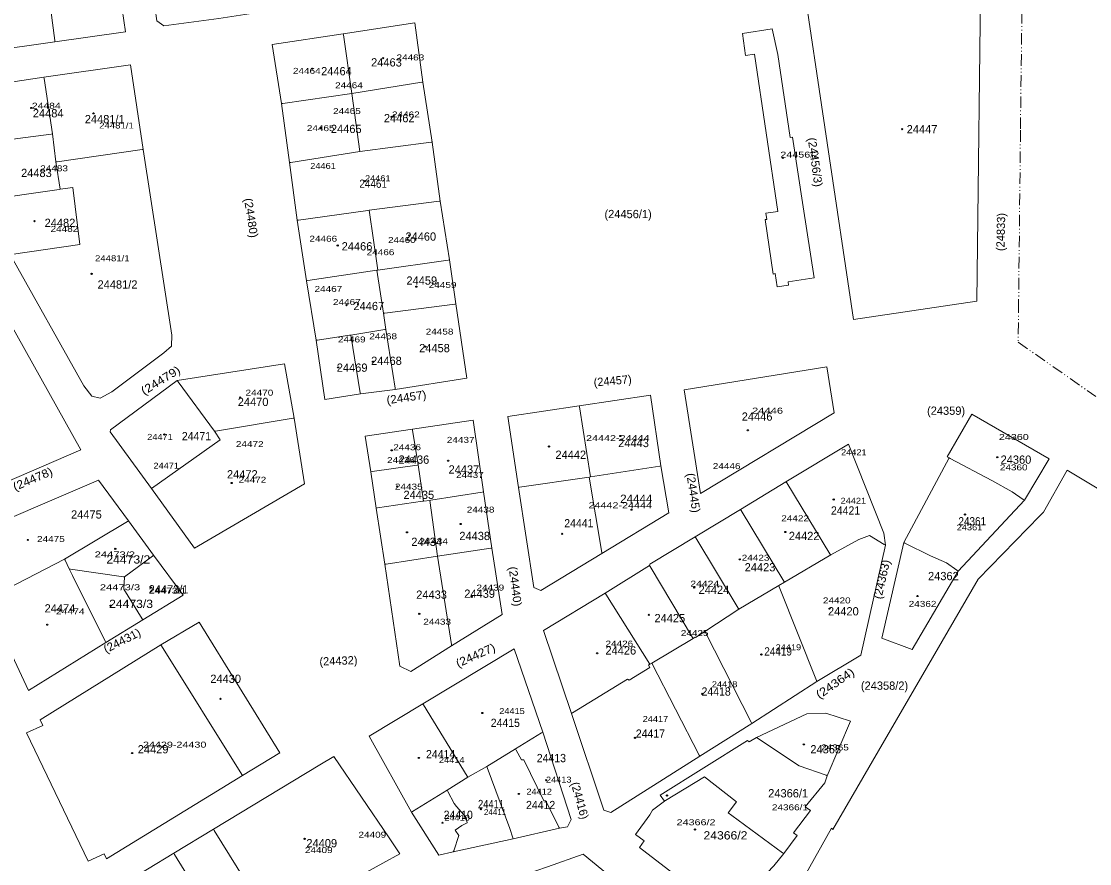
# Model space of a CAD drawing. Extents: x 649608 to 651081, y 237980 to 241202.
# Drawn here: x 650118.4 to 650584.2, y 239073.7 to 239440.9 of the extents above; entities that cross this region are included whole.
import ezdxf

# ---------------------------------------------------------------- set-up
doc = ezdxf.new("R2010")
doc.units = 0
doc.header["$PDMODE"] = 32
doc.header["$PDSIZE"] = 0.5
doc.linetypes.add('DASH_DOUBLE_DOT', pattern=[9.2, 5, -1.2, 0.3, -1.2, 0.3, -1.2])
for name, color, linetype in [('19', 7, 'Continuous'), ('20', 7, 'Continuous'), ('6', 7, 'Continuous')]:
    doc.layers.add(name, color=color, linetype=linetype)
for name, color, linetype, lineweight in [('3', 7, 'Continuous', 13), ('5', 7, 'Continuous', 13), ('52', 7, 'DASH_DOUBLE_DOT', 13)]:
    doc.layers.add(name, color=color, linetype=linetype, lineweight=lineweight)

msp = doc.modelspace()

# ---------------------------------------------------------------- linework, layer by layer
at = {"layer": '3'}
for p, q in [((650330.495, 239268.665), (650335.104, 239237.703)), ((650195.93, 239178.982), (650179.209, 239169.1)), ((650270.101, 239129.252), (650293.391, 239143.387))]:
    msp.add_line(p, q, dxfattribs=at)
for points in [[(650132.999, 239431.986), (650163.748, 239436.339), (650158.694, 239471.073), (650153.145, 239505.429)], [(650046.003, 239490.267), (650068.149, 239425.852), (650072.472, 239423.448), (650132.999, 239431.986)], [(650173.133, 239472.727), (650177.495, 239441.151), (650180.595, 239439.009), (650204.517, 239442.103), (650229.032, 239445.95)], [(650293.467, 239414.388), (650289.92, 239440.208), (650258.76, 239435.456), (650227.771, 239430.73)], [(650227.771, 239430.73), (650231.896, 239405.03), (650235.382, 239379.31), (650238.693, 239354.152), (650242.788, 239327.791), (650247.014, 239301.863), (650250.767, 239275.951)], [(650128.237, 239416.516), (650166.016, 239421.899), (650171.539, 239385.019)], [(650076.272, 239405.643), (650078.266, 239409.41), (650113.744, 239414.433), (650128.237, 239416.516)], [(650281.432, 239280.399), (650312.635, 239285.281), (650307.885, 239317.712), (650305.012, 239336.858), (650301.059, 239362.538), (650297.586, 239388.282), (650293.467, 239414.388)], [(650171.539, 239385.019), (650183.987, 239304.061), (650183.875, 239299.271), (650180.56, 239296.372), (650157.812, 239279.426), (650152.812, 239276.665), (650149.116, 239277.45), (650145.625, 239281.94), (650113.519, 239339.195), (650100.824, 239362.641), (650087.843, 239385.509), (650076.272, 239405.643)], [(650060.24, 239277.75), (650083.957, 239228.008), (650144.359, 239254.095), (650116.406, 239304.12), (650104.179, 239325.641)], [(650186.368, 239284.25), (650233.175, 239291.556), (650237.391, 239267.923)], [(650175.143, 239237.286), (650157.095, 239261.932), (650157.203, 239262.764), (650186.368, 239284.25)], [(650250.767, 239275.951), (650266.206, 239278.446), (650281.432, 239280.399)], [(650397.276, 239247.076), (650392.689, 239277.913), (650361.643, 239273.3), (650330.495, 239268.665)], [(650237.391, 239267.923), (650241.902, 239239.195), (650193.948, 239211.272), (650175.143, 239237.286)], [(650288.931, 239263.156), (650315.327, 239266.984), (650319.853, 239235.726), (650323.533, 239211.269)], [(650522.897, 239250.587), (650522.128, 239251.077), (650532.835, 239269.607)], [(650532.835, 239269.607), (650566.587, 239250.109), (650555.741, 239232.08), (650526.822, 239201.233)], [(650270.796, 239244.503), (650268.365, 239259.987), (650288.931, 239263.156)], [(650495.119, 239212.56), (650494.485, 239217.742), (650479.06, 239256.559), (650451.789, 239240.133), (650431.896, 239228.079), (650412.207, 239216.17)], [(650526.822, 239201.233), (650506.836, 239166.998), (650493.611, 239171.954), (650503.175, 239213.663), (650522.897, 239250.587)], [(650288.284, 239157.444), (650283.38, 239159.794), (650276.896, 239204.165), (650273.117, 239228.674), (650270.796, 239244.503)], [(650371.557, 239208.851), (650400.646, 239226.576), (650397.276, 239247.076)], [(650634.917, 238992.051), (650633.914, 238992.9), (650730.416, 239151.667), (650574.402, 239245.255), (650564.003, 239226.917), (650562.503, 239225.238), (650535.575, 239197.674), (650472.242, 239088.563), (650471.65, 239089.049), (650460.092, 239068.577)], [(650090.509, 239214.51), (650152.062, 239240.917), (650165.182, 239223.066), (650176.051, 239208.081)], [(650335.104, 239237.703), (650341.856, 239194.021), (650344.896, 239192.683), (650371.557, 239208.851)], [(650412.207, 239216.17), (650392.391, 239204.249), (650392.228, 239203.646), (650372.914, 239191.628)], [(650155.215, 239170.116), (650121.458, 239149.195), (650102.881, 239188.672), (650090.509, 239214.51)], [(650323.533, 239211.269), (650328.063, 239182.321), (650306.018, 239168.654), (650288.284, 239157.444)], [(650465.274, 239153.018), (650484.449, 239164.517), (650495.119, 239212.56)], [(650176.051, 239208.081), (650189.021, 239190.76), (650171.323, 239179.927), (650155.215, 239170.116)], [(650372.914, 239191.628), (650346.122, 239175.24), (650358.212, 239139.109)], [(650179.209, 239169.1), (650126.623, 239136.422), (650127.702, 239133.842), (650120.58, 239130.619), (650147.461, 239074.664), (650154.456, 239077.914), (650155.512, 239075.737), (650214.814, 239112.02), (650231.127, 239121.93), (650195.93, 239178.982)], [(650293.391, 239143.387), (650333.248, 239167.27), (650345.736, 239130.955)], [(650375.348, 239095.929), (650414.213, 239120.505), (650436.928, 239134.803), (650465.274, 239153.018)], [(650358.212, 239139.109), (650372.327, 239097.018), (650375.348, 239095.929)], [(650438.899, 239128.695), (650460.839, 239138.937), (650469.181, 239139.313), (650479.971, 239135.731), (650469.797, 239111.997)], [(650306.724, 239078.733), (650300.372, 239077.317), (650288.478, 239096.054), (650270.101, 239129.252)], [(650345.736, 239130.955), (650358.159, 239092.929), (650356.498, 239089.714), (650353.01, 239089.125), (650332.812, 239084.431), (650306.724, 239078.733)], [(650398.749, 239100.87), (650396.896, 239103.447), (650435.016, 239127.346), (650435.782, 239126.731), (650438.899, 239128.695)], [(650254.614, 239120.424), (650248.579, 239116.678), (650202.232, 239088.667), (650184.817, 239078.16)], [(650254.614, 239120.424), (650278.724, 239084.856), (650283.368, 239077.865), (650276.074, 239073.838)], [(650469.797, 239111.997), (650468.668, 239108.943), (650460.114, 239098.437), (650462.495, 239096.89), (650455.041, 239087.153), (650456.724, 239085.946), (650450.824, 239078.036)], [(650450.824, 239078.036), (650446.42, 239072.723), (650443.555, 239069.71), (650439.954, 239067.534), (650435.893, 239066.089), (650431.679, 239065.666), (650406.177, 239066.662), (650387.929, 239080.729), (650389.909, 239083.539), (650386.225, 239086.383), (650392.442, 239094.932), (650393.624, 239097.016), (650398.749, 239100.87)], [(650184.817, 239078.16), (650161.861, 239064.266), (650173.208, 239041.436)], [(650381.221, 239063.049), (650363.393, 239077.851), (650347.856, 239072.254), (650337.653, 239068.717)], [(650173.208, 239041.436), (650182.485, 239021.849), (650212.074, 239038.491), (650229.817, 239048.491), (650276.074, 239073.838)]]:
    msp.add_lwpolyline(points, dxfattribs=at)
for points in [[(650458.309, 239465.099), (650536.901, 239476.918), (650535.05, 239318.891), (650481.294, 239310.911)], [(650438.095, 239426.546), (650434.205, 239425.967), (650432.822, 239435.663), (650445.756, 239437.595), (650448.188, 239426.458), (650453.632, 239390.31), (650454.64, 239390.385), (650459.338, 239359.968), (650464.101, 239329.126), (650452.757, 239327.38), (650452.847, 239325.838), (650447.946, 239325.133), (650447.026, 239330.943), (650446.215, 239330.738), (650442.672, 239354.571), (650443.426, 239354.528), (650443.036, 239357.195), (650448.292, 239358.041)], [(650407.42, 239280.25), (650414.538, 239234.995), (650472.786, 239270.246), (650469.656, 239290.218)]]:
    msp.add_lwpolyline(points, close=True, dxfattribs=at)
at = {"layer": '5'}
for p, q in [((650273.859, 239332.471), (650270.036, 239358.518)), ((650273.415, 239332.408), (650273.859, 239332.471)), ((650102.881, 239188.672), (650137.202, 239206.437))]:
    msp.add_line(p, q, dxfattribs=at)
for points in [[(650132.999, 239431.986), (650132.935, 239432.486), (650128.533, 239466.816)], [(650258.76, 239435.456), (650258.819, 239435.048), (650262.488, 239409.451), (650266.022, 239384.128)], [(650128.237, 239416.516), (650128.311, 239416.016), (650131.91, 239391.803), (650133.48, 239379.637), (650135.357, 239367.722)], [(650262.488, 239409.451), (650292.967, 239414.308), (650293.467, 239414.388)], [(650262.488, 239409.451), (650232.396, 239405.102), (650231.896, 239405.03)], [(650131.91, 239391.803), (650131.41, 239391.734), (650116.932, 239389.749), (650087.843, 239385.509)], [(650266.022, 239384.128), (650297.086, 239388.216), (650297.586, 239388.282)], [(650171.539, 239385.019), (650171.039, 239384.948), (650133.98, 239379.708), (650133.48, 239379.637)], [(650266.022, 239384.128), (650235.882, 239379.389), (650235.382, 239379.31)], [(650135.357, 239367.722), (650134.857, 239367.648), (650101.324, 239362.715), (650100.824, 239362.641)], [(650135.357, 239367.722), (650140.827, 239368.411), (650143.963, 239343.627), (650114.019, 239339.268), (650113.519, 239339.195)], [(650270.036, 239358.518), (650300.559, 239362.473), (650301.059, 239362.538)], [(650270.036, 239358.518), (650269.536, 239358.448), (650239.193, 239354.222), (650238.693, 239354.152)], [(650273.859, 239332.471), (650304.512, 239336.788), (650305.012, 239336.858)], [(650273.415, 239332.408), (650243.288, 239327.866), (650242.788, 239327.791)], [(650281.432, 239280.399), (650281.353, 239280.899), (650277.315, 239306.605), (650276.347, 239313.633), (650273.415, 239332.408)], [(650276.347, 239313.633), (650276.847, 239313.698), (650307.385, 239317.647), (650307.885, 239317.712)], [(650262.001, 239304.107), (650276.815, 239306.523), (650277.315, 239306.605)], [(650262.001, 239304.107), (650261.501, 239304.032), (650247.514, 239301.938), (650247.014, 239301.863)], [(650266.206, 239278.446), (650266.124, 239278.946), (650262.001, 239304.107)], [(650202.572, 239262.164), (650186.735, 239283.75), (650186.368, 239284.25)], [(650361.643, 239273.3), (650361.723, 239272.8), (650366.622, 239242.311)], [(650202.572, 239262.164), (650203.072, 239262.247), (650236.891, 239267.84), (650237.391, 239267.923)], [(650288.931, 239263.156), (650289.01, 239262.656), (650291.407, 239247.473), (650293.78, 239231.717), (650296.457, 239232.051), (650299.787, 239207.752)], [(650175.143, 239237.286), (650205.149, 239258.463), (650202.572, 239262.164)], [(650522.897, 239250.587), (650523.397, 239250.321), (650541.494, 239240.686), (650550.391, 239235.807), (650555.241, 239232.428), (650555.741, 239232.08)], [(650270.796, 239244.503), (650271.296, 239244.575), (650290.907, 239247.401), (650291.407, 239247.473)], [(650366.622, 239242.311), (650396.776, 239246.998), (650397.276, 239247.076)], [(650335.104, 239237.703), (650335.604, 239237.776), (650366.023, 239242.218), (650366.622, 239242.311)], [(650366.023, 239242.218), (650371.474, 239209.351), (650371.557, 239208.851)], [(650471.278, 239208.225), (650470.973, 239208.725), (650452.094, 239239.633), (650451.789, 239240.133)], [(650296.457, 239232.051), (650296.957, 239232.13), (650319.353, 239235.647), (650319.853, 239235.726)], [(650273.117, 239228.674), (650273.617, 239228.748), (650293.28, 239231.643), (650293.78, 239231.717)], [(650451.189, 239196.375), (650450.885, 239196.875), (650432.2, 239227.579), (650431.896, 239228.079)], [(650137.202, 239206.437), (650164.682, 239222.769), (650165.182, 239223.066)], [(650431.197, 239184.578), (650430.896, 239185.078), (650412.508, 239215.67), (650412.207, 239216.17)], [(650471.278, 239208.225), (650483.522, 239215.043), (650488.242, 239216.671), (650494.619, 239212.859), (650495.119, 239212.56)], [(650299.787, 239207.752), (650323.033, 239211.195), (650323.533, 239211.269)], [(650503.175, 239213.663), (650503.675, 239213.415), (650514.845, 239207.874), (650521.796, 239204.804), (650526.322, 239201.588), (650526.822, 239201.233)], [(650137.202, 239206.437), (650137.444, 239205.937), (650139.264, 239202.185)], [(650163.444, 239198.697), (650175.551, 239207.709), (650176.051, 239208.081)], [(650276.896, 239204.165), (650277.396, 239204.243), (650299.787, 239207.752)], [(650299.787, 239207.752), (650305.938, 239169.154), (650306.018, 239168.654)], [(650411.341, 239171.797), (650412.197, 239172.449), (650412.318, 239172.192), (650416.372, 239174.908), (650431.197, 239184.578), (650448.636, 239194.87), (650451.189, 239196.375), (650471.278, 239208.225)], [(650139.264, 239202.185), (650140.698, 239199.35), (650154.967, 239170.616), (650155.215, 239170.116)], [(650139.264, 239202.185), (650139.764, 239202.113), (650162.944, 239198.769), (650163.444, 239198.697)], [(650411.341, 239171.797), (650411.041, 239172.297), (650392.528, 239203.146), (650392.228, 239203.646)], [(650171.323, 239179.927), (650171.012, 239180.427), (650163.021, 239193.254), (650163.444, 239198.697)], [(650448.636, 239194.87), (650448.835, 239194.37), (650465.075, 239153.518), (650465.274, 239153.018)], [(650392.443, 239160.617), (650373.229, 239191.128), (650372.914, 239191.628)], [(650416.372, 239174.908), (650416.628, 239174.408), (650436.672, 239135.303), (650436.928, 239134.803)], [(650358.212, 239139.109), (650358.712, 239139.415), (650382.744, 239154.124), (650383.392, 239153.627), (650392.438, 239159.14), (650391.903, 239160.196), (650392.443, 239160.617), (650393.287, 239161.058), (650411.341, 239171.797)], [(650179.209, 239169.1), (650179.521, 239168.6), (650214.502, 239112.52), (650214.814, 239112.02)], [(650393.287, 239161.058), (650413.955, 239121.005), (650414.213, 239120.505)], [(650293.391, 239143.387), (650293.699, 239142.887), (650312.821, 239111.85), (650313.129, 239111.35)], [(650333.91, 239123.656), (650345.236, 239130.646), (650345.736, 239130.955)], [(650438.899, 239128.695), (650457.463, 239116.286), (650469.297, 239112.171), (650469.797, 239111.997)], [(650288.478, 239096.054), (650288.978, 239096.361), (650304.084, 239105.65), (650313.129, 239111.35), (650321.295, 239116.052), (650333.91, 239123.656)], [(650333.91, 239123.656), (650334.18, 239123.156), (650336.472, 239118.913), (650337.433, 239118.918), (650346.234, 239101.106), (650347.017, 239101.013), (650352.758, 239089.625), (650353.01, 239089.125)], [(650321.295, 239116.052), (650321.482, 239115.552), (650331.384, 239089.011), (650332.656, 239084.931), (650332.812, 239084.431)], [(650398.749, 239100.87), (650399.249, 239101.171), (650416.291, 239111.439), (650430.235, 239100.653), (650426.596, 239095.745), (650428.105, 239094.642), (650450.324, 239078.401), (650450.824, 239078.036)], [(650304.084, 239105.65), (650304.344, 239105.15), (650307.095, 239099.865), (650308.17, 239098.499), (650312.363, 239093.73), (650312.737, 239091.436), (650310.444, 239090.272), (650307.525, 239088.18), (650309.185, 239085.979), (650306.894, 239079.233), (650306.724, 239078.733)], [(650215.882, 239066.55), (650202.541, 239088.167), (650202.232, 239088.667)], [(650184.817, 239078.16), (650185.127, 239077.66), (650197.855, 239057.151), (650198.165, 239056.651)]]:
    msp.add_lwpolyline(points, dxfattribs=at)
at = {"layer": '52'}
msp.add_lwpolyline([(650605.404, 240765.589), (650575.102, 240622.376), (650564.111, 240019.547), (650563.292, 239912.239), (650561.967, 239831.306), (650558.948, 239635.138), (650557.76, 239590.469), (650555.824, 239499.761), (650555.114, 239481.758), (650553.994, 239393.396), (650554.019, 239393.395), (650553.222, 239318.763), (650553.006, 239301.006), (650586.911, 239277.281)], dxfattribs=at)
at = {"layer": '6'}
for p in [(650276.158, 239424.829), (650245.198, 239420.243), (650122.715, 239403.132), (650149.879, 239400.768), (650279.882, 239399.258), (650248.965, 239394.38), (650502.425, 239393.914), (650450.427, 239381.364), (650268.168, 239371.217), (650124.142, 239353.803), (650287.513, 239347.504), (650256.346, 239343.154), (650149.036, 239330.842), (650290.644, 239325.245), (650260.162, 239317.135), (650294.559, 239299.055), (650256.518, 239290.029), (650271.713, 239292.525), (650213.793, 239276.86), (650435.178, 239262.606), (650180.746, 239260.768), (650379.549, 239260.112), (650279.868, 239253.829), (650348.479, 239255.501), (650304.495, 239249.35), (650543.906, 239250.843), (650210.128, 239239.597), (650282.281, 239238.073), (650472.59, 239232.392), (650384.403, 239227.963), (650529.837, 239225.91), (650309.914, 239221.739), (650286.557, 239218.108), (650354.183, 239217.45), (650451.514, 239218.254), (650121.217, 239214.794), (650159.35, 239210.881), (650431.628, 239206.328), (650174.836, 239194.004), (650411.785, 239193.983), (650314.745, 239189.961), (650509.141, 239190.33), (650157.35, 239186.15), (650470.793, 239184.844), (650291.922, 239182.598), (650392.017, 239182.131), (650129.691, 239177.816), (650369.438, 239165.368), (650441.055, 239164.836), (650415.246, 239147.706), (650205.257, 239145.501), (650319.383, 239139.31), (650385.932, 239128.493), (650459.549, 239125.655), (650166.72, 239121.882), (650291.675, 239119.72), (650347.194, 239110.04), (650335.279, 239104.043), (650399.923, 239103.365), (650318.7, 239097.392), (650302.054, 239091.483), (650412.119, 239088.552), (650241.91, 239084.457)]:
    msp.add_point(p, dxfattribs=at)

# ---------------------------------------------------------------- texts
at = {"layer": '19'}
for s, p in [('24464', (650249.092, 239417.37)), ('24463', (650270.894, 239421.209)), ('24484', (650123.404, 239399.027)), ('24481/1', (650146.061, 239396.466)), ('24462', (650276.452, 239396.893)), ('24465', (650253.367, 239392.2)), ('24447', (650504.418, 239392.073)), ('24483', (650118.274, 239373.004)), ('(24456/1)', (650372.643, 239355.085)), ('24482', (650128.534, 239351.246)), ('24460', (650285.858, 239345.272)), ('24466', (650258.07, 239341.007)), ('24481/2', (650151.619, 239324.369)), ('24459', (650286.285, 239326.075)), ('24467', (650263.201, 239314.984)), ('24458', (650291.843, 239296.639)), ('24469', (650255.933, 239288.107)), ('24468', (650270.895, 239291.094)), ('24470', (650212.754, 239273.176)), ('(24359)', (650513.295, 239269.336)), ('24446', (650432.495, 239266.776)), ('24443', (650378.628, 239255.258)), ('24442', (650351.267, 239250.139)), ('24436', (650282.866, 239248.005)), ('24360', (650545.357, 239248.006)), ('24472', (650208.052, 239241.607)), ('24437', (650304.669, 239243.739)), ('24435', (650285.004, 239232.647)), ('24475', (650140.076, 239224.116)), ('24434', (650288.424, 239212.17)), ('24438', (650309.372, 239214.73)), ('24422', (650453.016, 239214.731)), ('24423', (650433.778, 239201.079)), ('24362', (650513.723, 239197.24)), ('24473/1', (650173.895, 239191.462)), ('24433', (650290.561, 239189.133)), ('24439', (650311.509, 239189.56)), ('24424', (650413.685, 239191.267)), ('24474', (650128.534, 239183.161)), ('24420', (650470.116, 239181.882)), ('24425', (650394.447, 239178.895)), ('24426', (650373.071, 239164.817)), ('24430', (650200.784, 239152.446)), ('(24358/2)', (650484.448, 239149.462)), ('24429', (650169.147, 239121.73)), ('24365', (650462.421, 239121.729)), ('24366/1', (650444.038, 239102.532)), ('24409', (650242.679, 239080.775))]:
    msp.add_text(s, height=3.6, dxfattribs=at).set_placement(p)
for s, rotation, width, p in [('(24456/3)', 277.87, 1.05, (650461.252, 239389.971)), ('(24480)', 278.864, 1.05, (650215.461, 239363.535)), ('(24479)', 31.951, 1.15, (650171.95, 239277.796)), ('(24457)', 8.252, 1.05, (650277.91, 239273.939)), ('(24478)', 23.35, 1.1, (650115.688, 239236.11)), ('(24445)', 278.55, 1.05, (650408.357, 239243.676)), ('(24440)', 277.447, 1.05, (650330.856, 239202.939)), ('(24363)', 77.085, 1.05, (650493.356, 239188.738)), ('(24431)', 27.059, 1.05, (650155.354, 239165.313)), ('(24427)', 24.578, 1.1, (650308.867, 239159.072)), ('(24364)', 35.193, 1.15, (650466.417, 239145.331))]:
    msp.add_text(s, height=3.6, rotation=rotation, dxfattribs=dict(at, width=width)).set_placement(p)
for s, width, p in [('24461', 0.9, (650265.764, 239368.31)), ('24471', 0.95, (650188.386, 239258.245)), ('24444', 1.05, (650379.482, 239230.942)), ('24421', 0.95, (650471.399, 239225.823)), ('24441', 0.95, (650355.115, 239220.276)), ('24361', 0.9, (650526.975, 239221.13)), ('24473/2', 1.1, (650155.467, 239204.492)), ('24473/3', 1.1, (650156.663, 239185.124)), ('24419', 0.9, (650442.327, 239164.391)), ('24418', 0.95, (650414.967, 239146.9)), ('24415', 0.95, (650323.053, 239133.247)), ('24417', 0.95, (650386.323, 239128.555)), ('24414', 0.95, (650294.838, 239119.595)), ('24413', 0.95, (650343.146, 239117.89)), ('24411', 0.85, (650317.495, 239097.839)), ('24412', 0.95, (650338.443, 239097.412)), ('24410', 0.95, (650302.532, 239093.146)), ('24366/2', 1.1, (650415.821, 239084.187))]:
    msp.add_text(s, height=3.6, dxfattribs=dict(at, width=width)).set_placement(p)
for s, rotation, p in [('(24833)', 88.718, (650547.041, 239340.718)), ('(24457)', 4.998, (650368.09, 239281.691)), ('(24432)', 2.298, (650248.433, 239159.975)), ('(24416)', 285.699, (650357.944, 239108.665))]:
    msp.add_text(s, height=3.6, rotation=rotation, dxfattribs=at).set_placement(p)
at = {"layer": '20'}
for s, width, p in [('24463', 1.25, (650281.982, 239423.857)), ('24464', 1.25, (650236.806, 239418.007)), ('24464', 1.25, (650255.19, 239411.724)), ('24484', 1.3, (650122.979, 239402.807)), ('24465', 1.25, (650254.297, 239400.472)), ('24462', 1.25, (650279.99, 239398.993)), ('24481/1', 1.2, (650152.337, 239394.177)), ('24465', 1.25, (650242.873, 239393.029)), ('24456/2', 1.35, (650449.31, 239381.488)), ('24461', 1.15, (650244.371, 239376.561)), ('24483', 1.25, (650126.636, 239375.505)), ('24461', 1.15, (650268.239, 239371.186)), ('24482', 1.25, (650131.133, 239349.103)), ('24466', 1.25, (650244.006, 239344.825)), ('24460', 1.25, (650278.263, 239344.28)), ('24466', 1.25, (650268.962, 239338.948)), ('24481/1', 1.2, (650150.525, 239336.322)), ('24467', 1.25, (650246.235, 239322.942)), ('24459', 1.25, (650296.034, 239324.696)), ('24467', 1.25, (650254.266, 239317.197)), ('24468', 1.25, (650270.118, 239302.283)), ('24458', 1.25, (650294.714, 239304.328)), ('24469', 1.25, (650256.411, 239300.9)), ('24470', 1.25, (650216.159, 239277.693)), ('24446 ', 1.4, (650436.981, 239269.866)), ('24471', 1.15, (650173.283, 239258.419)), ('24472', 1.25, (650211.94, 239255.282)), ('24437', 1.25, (650303.911, 239257.12)), ('24442-24444', 1.35, (650364.622, 239257.871)), ('24360 ', 1.35, (650544.597, 239258.381)), ('24436', 1.25, (650280.566, 239253.914)), ('24421', 1.15, (650475.808, 239251.719)), ('24471', 1.15, (650176.001, 239245.851)), ('24436', 1.25, (650277.853, 239248.284)), ('24437', 1.25, (650307.922, 239241.832)), ('24446', 1.25, (650419.866, 239245.677)), ('24360', 1.25, (650545.032, 239245.113)), ('24472', 1.25, (650213.08, 239239.709)), ('24435', 1.25, (650281.28, 239236.728)), ('24442-24444', 1.35, (650365.694, 239228.614)), ('24421', 1.15, (650475.62, 239230.579)), ('24438', 1.25, (650312.597, 239226.712)), ('24422', 1.25, (650449.732, 239222.951)), ('24361', 1.15, (650526.246, 239218.975)), ('24475', 1.25, (650125.239, 239213.893)), ('24434', 1.3, (650291.88, 239212.893)), ('24473/2', 1.4, (650150.375, 239207.177)), ('24423', 1.25, (650432.482, 239205.721)), ('24473/3', 1.4, (650152.621, 239192.853)), ('24473/1', 1.3, (650173.956, 239191.345)), ('24439', 1.25, (650316.835, 239192.718)), ('24424', 1.3, (650410.097, 239194.426)), ('24420', 1.25, (650467.878, 239187.106)), ('24362', 1.25, (650505.287, 239185.613)), ('24474', 1.3, (650133.438, 239182.298)), ('24433', 1.25, (650293.654, 239177.838)), ('24425', 1.25, (650405.935, 239172.888)), ('24426', 1.25, (650373.082, 239168.284)), ('24419', 1.15, (650447.282, 239166.685)), ('24418', 1.15, (650419.467, 239150.588)), ('24415', 1.15, (650326.759, 239138.859)), ('24417', 1.15, (650389.315, 239135.447)), ('24429-24430', 1.35, (650171.411, 239124.246)), ('24365', 1.25, (650467.117, 239123.01)), ('24414', 1.15, (650300.489, 239117.53)), ('24413', 1.15, (650347.148, 239108.98)), ('24412', 1.15, (650338.614, 239103.761)), ('24366/1', 1.25, (650445.655, 239096.91)), ('24410', 1.15, (650302.825, 239092.331)), ('24366/2', 1.35, (650404.087, 239090.391)), ('24409', 1.25, (650265.395, 239084.961)), ('24409', 1.25, (650242.029, 239078.257))]:
    msp.add_text(s, height=2.6, dxfattribs=dict(at, width=width)).set_placement(p)
msp.add_text('24411', height=2.6, dxfattribs=at).set_placement((650320.089, 239094.851))

doc.saveas('drawing.dxf')
